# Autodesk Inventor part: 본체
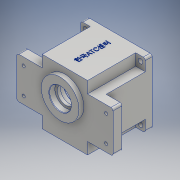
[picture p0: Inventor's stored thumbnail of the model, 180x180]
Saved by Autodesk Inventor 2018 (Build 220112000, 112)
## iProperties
Created: 2020-07
Part Number: 본체
Material: 알루미늄 6061
Document SubType Name: Modeling
Designer: admin
Density: 2.7 g/cm^3
Appearance: 알루미늄 - 평지
Mass: 876.465 g
Surface Area: 793.597 cm^2
Volume: 324.617 cm^3
Author: admin
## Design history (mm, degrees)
sketch "스케치1"
  geometry: L1 (47, -47)-(-47, -47); L2 (-47, -47)-(-47, 47); L3 (-47, 47)-(47, 47); L4 (47, 47)-(47, -47); L5 (47, -47)-(-47, 47); L6 (-47, -47)-(47, 47); 1 further point
  constraints: 12 end point, 2 midpoint, 2 parallel, 1 horizontal, 1 perpendicular
  dimensions: "d0" = 94 distance of L1.end L2.end; "d1" = 94 distance of L2.end L3.end
extrude "돌출1" new body sketch "스케치1" distance "d2" = 80; taper "d3" = 0 deg
sketch "스케치2"
  geometry: L1 (-98, 0)-(98, 0) reference; L2 (0, -65.8)-(0, 65.8) reference; L3 (-47, -47)-(47, -47) reference; L4 (47, -47)-(47, 47) reference; L5 (47, 47)-(-47, 47) reference; L6 (-47, 47)-(-47, -47) reference; L7 (-70, 30)-(70, 30); L8 (70, 30)-(70, -30); L9 (70, -30)-(-70, -30); L10 (-70, -30)-(-70, 30); 1 further point
  constraints: 8 end point, 2 parallel, 1 horizontal, 1 perpendicular, 2 other
  dimensions: "d4" = 140 distance of L7.start L7.end; "d5" = 60 distance of L7.end L8.end
extrude "돌출2" join sketch "스케치2" distance "d6" = 13; taper "d7" = 0 deg
sketch "스케치3"
  geometry: L1 (-47, -30)-(-47, -47) reference; L2 (-47, -47)-(47, -47) reference; L3 (47, -47)-(47, -30) reference; L4 (70, -30)-(47, -30) reference; L5 (70, 30)-(70, -30) reference; L6 (47, 30)-(70, 30) reference; L7 (47, 30)-(47, 47) reference; L8 (47, 47)-(-47, 47) reference; L9 (-47, 47)-(-47, 30) reference; L10 (-70, 30)-(-47, 30) reference; L11 (-70, -30)-(-70, 30) reference; L12 (-47, -30)-(-70, -30) reference; L13 (-98, 0)-(98, 0) reference; L14 (0, -65.8)-(0, 65.8) reference; L15 (-47, 47)-(-33, 47); L16 (-33, 47)-(-33, 30); L17 (-33, 30)-(-47, 30); L18 (-47, 30)-(-47, 47); L19 (47, 47)-(33, 47); L20 (47, 30)-(47, 47); L21 (33, 30)-(47, 30); L22 (33, 47)-(33, 30); L23 (-33, -47)-(-33, -30); L24 (-33, -30)-(-47, -30); L25 (-47, -47)-(-33, -47); L26 (-47, -30)-(-47, -47); L27 (33, -30)-(47, -30); L28 (47, -30)-(47, -47); L29 (33, -47)-(33, -30); L30 (47, -47)-(33, -47); 1 further point
  constraints: 32 end point, 12 symmetric about line, 2 parallel, 1 horizontal, 1 perpendicular
  dimensions: "d8" = 66 distance between parallel lines of L22 L16; "d9" = 60 distance between parallel lines of L27 L21
extrude "돌출3" cut sketch "스케치3" distance "d10" = 70; taper "d11" = 0 deg
sketch "스케치4"
  geometry: L1 (0, -65.8)-(0, 65.8) reference; L2 (-98, 0)-(98, 0) reference; L3 (-33, -30)-(-33, -47) reference; L4 (-33, -47)-(33, -47) reference; L5 (33, -47)-(33, -30) reference; L6 (70, -30)-(33, -30) reference; L7 (70, 30)-(70, -30) reference; L8 (70, 30)-(33, 30) reference; L9 (33, 30)-(33, 47) reference; L10 (33, 47)-(-33, 47) reference; L11 (-33, 47)-(-33, 30) reference; L12 (-70, 30)-(-33, 30) reference; L13 (-70, -30)-(-70, 30) reference; L14 (-70, -30)-(-33, -30) reference; C1 r 27.5 at (0, 11); 1 further point
  constraints: 1 centre point, 1 point on line
  dimensions: "d12" = 55 diameter of C1; "d13" = 11 distance from line of L2 C1.centre
extrude "돌출4" join sketch "스케치4" distance "d14" = 7; taper "d15" = 0 deg
sketch "스케치5"
  geometry: C1 r 43 at (0, 0); 1 further point
  constraints: 1 centre point, 1 coincident
  dimensions: "d16" = 86 diameter of C1
extrude "돌출5" cut sketch "스케치5" distance "d17" = 9; taper "d18" = 0 deg
sketch "스케치6" dims "d21" = 36
  geometry: L1 (-137.2, 0)-(137.2, 0) reference; L2 (0, 65.8)-(0, -65.8) reference; L3 (137.2, 0)-(-137.2, 0); A1 r 40 centre (0, 0) between (39.279, 7.559) and (-39.279, 7.559); A2 r 4 centre (36, 0) between (36.19, 3.995) and (36.19, -3.995); A3 r 3 centre (36.333, -6.992) between (39.279, -7.559) and (36.19, -3.995); A4 r 3 centre (36.333, 6.992) between (36.19, 3.995) and (39.279, 7.559); A5 r 4 centre (-36, 0) between (-36.19, -3.995) and (-36.19, 3.995); A6 r 3 centre (-36.333, -6.992) between (-36.19, -3.995) and (-39.279, -7.559); A7 r 3 centre (-36.333, 6.992) between (-39.279, 7.559) and (-36.19, 3.995); A8 r 40 centre (0, 0) between (-39.279, -7.559) and (39.279, -7.559); A9 r 40 centre (0, 0) between (39.279, 7.559) and (-39.279, 7.559); A10 r 40 centre (0, 0) between (-39.279, -7.559) and (39.279, -7.559); A11 r 40 centre (0, 0) between (-39.279, 7.559) and (-39.279, -7.559); 2 further points
  constraints: 22 point on circle, 12 symmetric about line, 11 centre point, 3 coincident, 2 end point, 2 horizontal alignment, 2 point on line, 2 tangent, 1 vertical, 8 other
  dimensions: "d19" = 80 diameter of A1; "d23" = 8 diameter of A2; "d24" = 3 radius of A3
extrude "돌출6" cut sketch "스케치6" distance "d26" = 62; taper "d27" = 0 deg
sketch "스케치7"
  geometry: C1 r 27.5 at (0, 0) reference; C2 r 16 at (0, 0); 1 further point
  constraints: 1 centre point, 1 coincident
  dimensions: "d28" = 32 diameter of C2
extrude "돌출7" cut sketch "스케치7" distance "d29" = 8.3; taper "d30" = 0 deg
chamfer "모따기1" distance "d31" = 0.8; stored, may be unused: second distance "d32" = 2, angle "d33" = 30 deg
sketch "스케치8"
  geometry: L1 (47, 47)-(-47, 47) reference; L2 (-47, 47)-(-47, -47) reference; L3 (-47, -47)-(47, -47) reference; L4 (47, -47)-(47, 47) reference; L5 (-47, 30)-(-47, -30) reference; L6 (-47, 30)-(-70, 30) reference; L7 (-70, 30)-(-70, -30) reference; L8 (-70, -30)-(-47, -30) reference; L9 (47, -30)-(47, 30) reference; L10 (47, -30)-(70, -30) reference; L11 (70, -30)-(70, 30) reference; L12 (70, 30)-(47, 30) reference; L13 (-98, 0)-(98, 0) reference; L14 (0, 65.8)-(0, -65.8) reference; C1 r 43 at (0, 0) reference; C2 r 43 at (0, 0) reference; A1 r 3 centre (36.333, -6.992) between (39.279, -7.559) and (36.19, -3.995) reference; A2 r 4 centre (36, 0) between (36.19, 3.995) and (36.19, -3.995) reference; A3 r 3 centre (36.333, 6.992) between (36.19, 3.995) and (39.279, 7.559) reference; A4 r 40 centre (0, 0) between (39.279, 7.559) and (-39.279, 7.559) reference; A5 r 3 centre (-36.333, 6.992) between (-39.279, 7.559) and (-36.19, 3.995) reference; A6 r 4 centre (-36, 0) between (-36.19, -3.995) and (-36.19, 3.995) reference; A7 r 3 centre (-36.333, -6.992) between (-36.19, -3.995) and (-39.279, -7.559) reference; A8 r 40 centre (0, 0) between (-39.279, -7.559) and (39.279, -7.559) reference; A9 r 21 centre (0, -11) between (-12.163, 6.119) and (12.163, 6.119); A10 r 15 centre (0, 20) between (11.584, 10.47) and (-11.584, 10.47); A11 r 3 centre (-13.901, 8.565) between (-12.163, 6.119) and (-11.584, 10.47); A12 r 3 centre (13.901, 8.565) between (11.584, 10.47) and (12.163, 6.119); 1 further point
  constraints: 8 point on circle, 4 centre point, 4 tangent, 2 point on line, 1 equal radius
  dimensions: "d34" = 21 radius of A9; "d35" = 11 distance from line of L13 A9.centre; "d36" = 15 radius of A10; "d37" = 20 distance from line of L13 A10.centre; "d38" = 3 radius of A11
extrude "돌출8" join sketch "스케치8" distance "d39" = 7; taper "d40" = 0 deg
sketch "스케치9"
  geometry: C1 r 17.5 at (0, -11); A1 r 3 centre (-13.901, 8.565) between (-12.163, 6.119) and (-11.584, 10.47) reference; A2 r 21 centre (0, -11) between (-12.163, 6.119) and (12.163, 6.119) reference; A3 r 3 centre (13.901, 8.565) between (11.584, 10.47) and (12.163, 6.119) reference; A4 r 15 centre (0, 20) between (11.584, 10.47) and (-11.584, 10.47) reference; 1 further point
  constraints: 1 centre point, 1 coincident
  dimensions: "d41" = 35 diameter of C1
extrude "돌출9" cut sketch "스케치9" distance "d42" = 10; taper "d43" = 0 deg
sketch "스케치10"
  geometry: C1 r 17.5 at (0, 0) reference; C2 r 12.5 at (0, 0); 1 further point
  constraints: 1 centre point, 1 coincident
  dimensions: "d44" = 25 diameter of C2
extrude "돌출10" cut sketch "스케치10" distance "d45" = 4.7; taper "d46" = 0 deg
sketch "스케치11"
  geometry: C1 r 17.5 at (0, -11) reference; C2 r 11 at (0, 20); A1 r 3 centre (-13.901, 8.565) between (-12.163, 6.119) and (-11.584, 10.47) reference; A2 r 21 centre (0, -11) between (-12.163, 6.119) and (12.163, 6.119) reference; A3 r 3 centre (13.901, 8.565) between (11.584, 10.47) and (12.163, 6.119) reference; A4 r 15 centre (0, 20) between (11.584, 10.47) and (-11.584, 10.47) reference; 1 further point
  constraints: 1 centre point, 1 coincident
  dimensions: "d47" = 22 diameter of C2
extrude "돌출11" cut sketch "스케치11" distance "d48" = 7; taper "d49" = 0 deg
sketch "스케치12"
  geometry: C1 r 11 at (0, 0) reference; C2 r 9.5 at (0, 0); 1 further point
  constraints: 1 centre point, 1 coincident
  dimensions: "d50" = 19 diameter of C2
extrude "돌출12" cut sketch "스케치12" distance "d51" = 3; taper "d52" = 0 deg
fillet "모깎기1" dims "d53" = 3
sketch "스케치13"
  geometry: L1 (-33, 30)-(-33, 47) reference; L2 (-33, 47)-(33, 47) reference; L3 (33, 47)-(33, 30) reference; L4 (70, 30)-(33, 30) reference; L5 (70, -30)-(70, 30) reference; L6 (70, -30)-(33, -30) reference; L7 (33, -30)-(33, -47) reference; L8 (33, -47)-(-33, -47) reference; L9 (-33, -47)-(-33, -30) reference; L10 (-70, -30)-(-33, -30) reference; L11 (-70, 30)-(-70, -30) reference; L12 (-70, 30)-(-33, 30) reference; L13 (0, 65.8)-(0, -65.8) reference; L14 (-98, 0)-(98, 0) reference; C1 r 27.5 at (0, -11) reference; 5 further points
  constraints: 2 horizontal alignment, 2 symmetric about line, 2 vertical alignment
  dimensions: "d54" = 120 distance of point (60, -19) point (-60, -19); "d55" = 38 distance of point (-60, 19) point (-60, -19)
hole "구멍1" sketch "스케치13" at (60, -19), (-60, -19), (-60, 19), (60, 19) diameter "d56" = 4.5; stored, may be unused: countersink angle "d60" = 90 deg, drill point angle "d62" = 0 deg; dims "d57" = 6, "d58" = 10, "d59" = 5, "d61" = 30
sketch "스케치14"
  geometry: L1 (47, -47)-(-47, -47) reference; L2 (-47, -47)-(-47, 47) reference; L3 (-47, 47)-(47, 47) reference; L4 (47, 47)-(47, -47) reference; L5 (-98, 0)-(98, 0) reference; L6 (0, -65.8)-(0, 65.8) reference; C1 r 43 at (0, 0) reference; C2 r 3.5 at (-40, 40); C3 r 3.5 at (40, 40); C4 r 3.5 at (-40, -40); C5 r 3.5 at (40, -40); 1 further point
  constraints: 4 centre point, 3 symmetric about line, 3 other
  dimensions: "d63" = 80 distance of C3.centre C2.centre; "d64" = 80 distance of C5.centre C3.centre; "d65" = 7 diameter of C3
extrude "돌출13" cut sketch "스케치14" extent not by distance; stored distance "d66" = 3; taper "d67" = 0 deg
sketch "스케치15"
  geometry: C1 r 43 at (0, 0) reference; A1 r 4 centre (36, 0) between (36.19, 3.995) and (36.19, -3.995) reference; A2 r 3 centre (36.333, -6.992) between (39.279, -7.559) and (36.19, -3.995) reference; A3 r 40 centre (0, 0) between (-39.279, -7.559) and (39.279, -7.559) reference; A4 r 3 centre (-36.333, -6.992) between (-36.19, -3.995) and (-39.279, -7.559) reference; A5 r 4 centre (-36, 0) between (-36.19, -3.995) and (-36.19, 3.995) reference; A6 r 3 centre (-36.333, 6.992) between (-39.279, 7.559) and (-36.19, 3.995) reference; A7 r 40 centre (0, 0) between (39.279, 7.559) and (-39.279, 7.559) reference; A8 r 3 centre (36.333, 6.992) between (36.19, 3.995) and (39.279, 7.559) reference; 3 further points
  constraints: 2 coincident
hole "구멍2" sketch "스케치15" at (36, 0), (-36, 0) diameter "d68" = 3.242; stored, may be unused: countersink angle "d72" = 90 deg, drill point angle "d74" = 118 deg; dims "d69" = 7, "d70" = 10, "d71" = 5, "d73" = 9
fillet "모깎기2" dims "d75" = 3
chamfer "모따기2" distance "d76" = 1; stored, may be unused: second distance "d77" = 2, angle "d78" = 30 deg
sketch "스케치16"
  geometry: L1 (33, -24.4)-(33, 97.4) reference; L2 (-11, 80)-(77, 80) reference; 2 further points
  constraints: 1 point on line, 1 other
  dimensions: "d79" = 40 distance from line of L2 point (33, 40)
feature "엠보싱1" sketch "스케치16" dims "d0" = 94, "d1" = 94, "d80" = 0.5, "d81" = 0
node "솔리드1"
node "투영된 루프1"
node "투영된 루프2"
node "투영된 루프3"
node "투영된 루프4"
node "투영된 루프5"
node "투영된 루프6"
node "투영된 루프7"
node "투영된 루프8"
node "투영된 루프9"
node "투영된 루프10"
node "투영된 루프11"
node "투영된 루프12"
node "투영된 루프13"
node "투영된 루프14"
node "투영된 루프15"
